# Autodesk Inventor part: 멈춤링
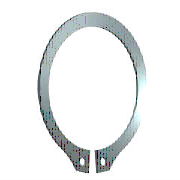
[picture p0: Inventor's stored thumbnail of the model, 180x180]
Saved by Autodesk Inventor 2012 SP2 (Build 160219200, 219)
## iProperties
IsCustomPart: 0
Created: 2009-02
Part Number: 멈춤링
Material: 강, 연강
Description: 리테이닝 링(C형)
Document SubType Name: Modeling
Standard: KS B 1336
Designer: KYOUNG IL JANG
Standards Organization: KS
Language: ko-KR
Size Designation: 22 x 1.2
Categories: <MemberInstance><Categories><Category DisplayName="샤프트 부품" InternalName="7f7aeb1f-a693-4053-b835-cee3144e0d98" Mnemonic="SHFT"><Category DisplayName="써클립" Inter
Density: 1 g/cm^3
Author: KYOUNG IL JANG
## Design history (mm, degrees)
sketch "스케치1"
  geometry: L1 (-6, 0)-(6, 0) reference; L2 (0, 20.189)-(0, -80.536) reference; L3 (-48.09, 0)-(48.09, 0) reference; L4 (-0.5, -21.488)-(-0.5, -25.588); L5 (-0.5, -6.54)-(-0.5, -13.29); L6 (-2.795, 2.7)-(3.672, 2.7); L7 (0.5, -6.54)-(0.5, -13.29); L8 (0.5, -21.488)-(0.5, -25.588); C1 r 1 at (-2, -23.437); C2 r 1 at (2, -23.437); A1 r 10.5 centre (0, -11) between (0.5, -21.488) and (-0.5, -21.488); A2 r 13.025 centre (0, -10.325) between (5.149, -22.289) and (-5.149, -22.289); A3 r 14.597 centre (0, -11) between (-2.318, -25.411) and (-0.5, -25.588); A4 r 2 centre (-2, -23.437) between (-3.97, -23.781) and (-2.318, -25.411); A5 r 2 centre (-5.94, -24.126) between (-3.97, -23.781) and (-5.149, -22.289); A6 r 2 centre (5.94, -24.126) between (5.149, -22.289) and (3.97, -23.781); A7 r 2 centre (2, -23.437) between (2.318, -25.411) and (3.97, -23.781); A8 r 14.597 centre (0, -11) between (0.5, -25.588) and (2.318, -25.411)
  constraints: 16 point on circle, 12 end point, 10 centre point, 9 symmetric about line, 5 point on line, 4 tangent, 3 coincident, 2 horizontal, 1 perpendicular, 1 vertical, 5 other
  dimensions: "d0" = 21 diameter of A1 (= ND); "d1" = 4.1 distance of L4.end L4.start (= SRB2); "d6" = 0.5 distance between parallel lines of L2 L5 (= 0.25 x SD5); "d7" = 2.7 distance between parallel lines of L6 L3 (= SRB1); "d8" = 0.675 distance of A1.centre A2.centre (= 0.25 x SRB1); "d9" = 2 radius of A4 (= SD5); "d10" = 2 radius of A5 (= SD5); "d11" = 1.5 distance from line of L4 A4.centre (= 0.75 x SD5); "d12" = 2 diameter of C1 (= SD5); "d13" = 2 diameter of C2 (= SD5); "d14" = 11 distance from line of A1.centre L1 (= 0.5 x WD)
extrude "본체" new body sketch "스케치1" distance "d2" = 1.2 (= SD); taper "d3" = 0 deg
workaxis "Work Axis1"
workplane "Work Plane1"
body "Solid1"
other parameters: "WD" = 22 (= WDMIN) [user parameter; used in 1 equation term], "SD" = 1.2 [user parameter; used in 1 equation term], "SRB1" = 2.7 [user parameter; used in 2 equation terms], "ND" = 21 [user parameter; used in 1 equation term], "SRB2" = 4.1 [user parameter; used in 1 equation term], "SD5" = 2 [user parameter; used in 6 equation terms], "d15" = 0, "d16" = 0, "d17" = 0, "d41" = 0, "d42" = 0, "WDMIN" = 22 [user parameter; used in 1 equation term], "SD3" = 20.5 [user parameter], "WDMAX" = 24 [user parameter]
